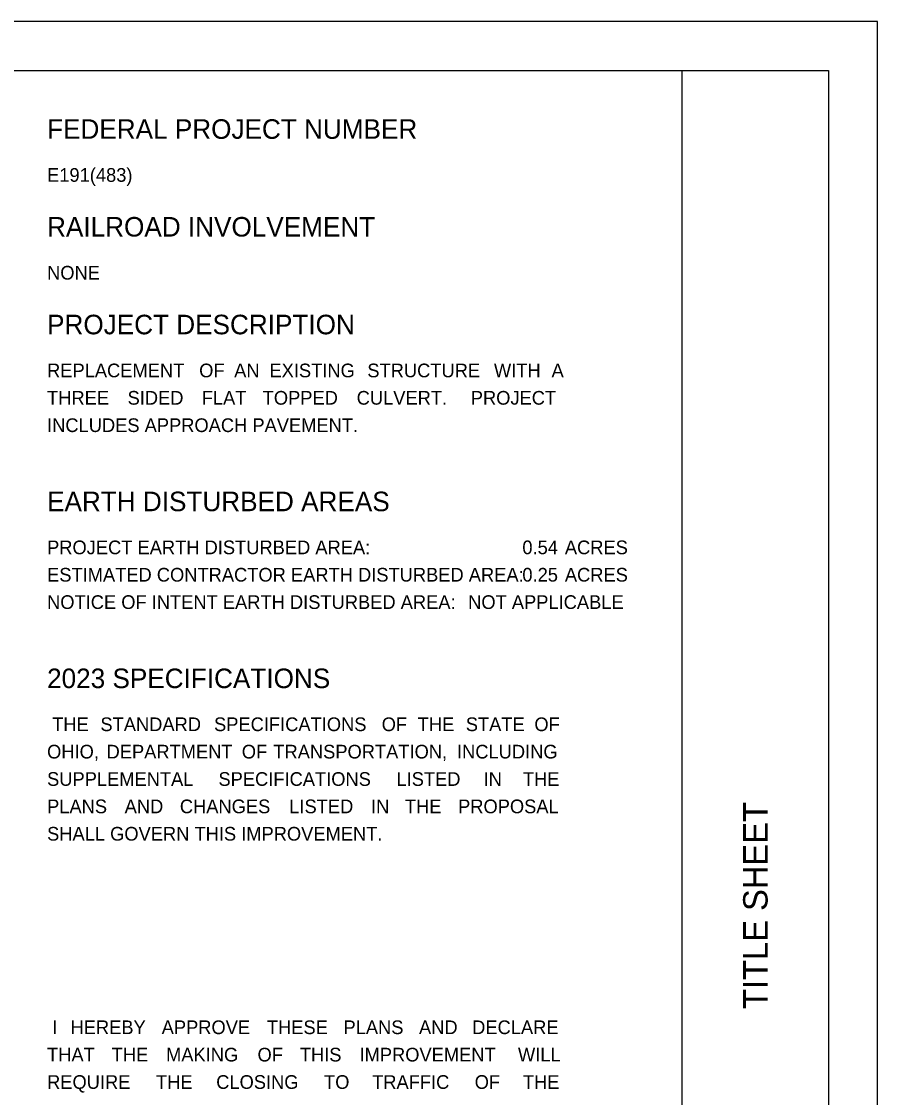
# Model space of a CAD drawing. Extents: x -6.4 to 34, y -1.2 to 22.
# Drawn here: x 25.24 to 34, y 10.99 to 22 of the extents above; entities that cross this region are included whole.
import ezdxf

# ---------------------------------------------------------------- set-up
doc = ezdxf.new("R2010")
doc.units = 0
for name, color, linetype in [('GM_X_County', 7, 'Continuous'), ('GM_X_Section', 7, 'Continuous'), ('GM_X_Township', 7, 'Continuous')]:
    doc.layers.add(name, color=color, linetype=linetype)

msp = doc.modelspace()

# ---------------------------------------------------------------- linework, layer by layer
at = {"layer": 'GM_X_County'}
msp.add_line((32, 0.5), (32, 21.5), dxfattribs=at)
msp.add_lwpolyline([(1.5, 21.5), (33.5, 21.5), (33.5, 0.5), (1.5, 0.5)], close=True, dxfattribs=at)
at = {"layer": 'GM_X_Section'}
msp.add_lwpolyline([(0, 0), (34, 0), (34, 22), (0, 22)], close=True, dxfattribs=at)

# ---------------------------------------------------------------- texts
at = {"layer": 'GM_X_Township'}
for s, height, p in [('FEDERAL PROJECT NUMBER', 0.2, (25.5, 20.8)), ('E191(483)', 0.14, (25.5, 20.36)), ('RAILROAD INVOLVEMENT', 0.2, (25.5, 19.8)), ('NONE', 0.14, (25.5, 19.36)), ('PROJECT DESCRIPTION', 0.2, (25.5, 18.8)), ('REPLACEMENT ', 0.14, (25.5, 18.36)), ('OF ', 0.14, (27.057, 18.36)), ('AN ', 0.14, (27.415, 18.36)), ('EXISTING ', 0.14, (27.776, 18.36)), ('STRUCTURE ', 0.14, (28.778, 18.36)), ('WITH ', 0.14, (30.074, 18.36)), ('A ', 0.14, (30.664, 18.36)), ('THREE ', 0.14, (25.5, 18.08)), ('SIDED ', 0.14, (26.324, 18.08)), ('FLAT ', 0.14, (27.083, 18.08)), ('TOPPED ', 0.14, (27.707, 18.08)), ('CULVERT.  ', 0.14, (28.669, 18.08)), ('PROJECT ', 0.14, (29.837, 18.08)), ('INCLUDES APPROACH PAVEMENT.', 0.14, (25.5, 17.8)), ('EARTH DISTURBED AREAS', 0.2, (25.5, 16.99)), ('PROJECT EARTH DISTURBED AREA:', 0.14, (25.5, 16.55)), ('0.54 ', 0.14, (30.365, 16.55)), ('ACRES', 0.14, (30.8, 16.55)), ('ESTIMATED CONTRACTOR EARTH DISTURBED AREA:', 0.14, (25.5, 16.27)), ('0.25 ', 0.14, (30.365, 16.27)), ('ACRES', 0.14, (30.8, 16.27)), ('NOTICE OF INTENT EARTH DISTURBED AREA:', 0.14, (25.5, 15.99)), ('NOT APPLICABLE', 0.14, (29.81, 15.99)), ('2023 SPECIFICATIONS', 0.2, (25.5, 15.18)), (' THE ', 0.14, (25.5, 14.74)), ('STANDARD ', 0.14, (26.046, 14.74)), ('SPECIFICATIONS ', 0.14, (27.209, 14.74)), ('OF ', 0.14, (28.925, 14.74)), ('THE ', 0.14, (29.294, 14.74)), ('STATE ', 0.14, (29.786, 14.74)), ('OF ', 0.14, (30.488, 14.74)), ('OHIO, ', 0.14, (25.5, 14.46)), ('DEPARTMENT ', 0.14, (26.109, 14.46)), ('OF ', 0.14, (27.493, 14.46)), ('TRANSPORTATION, ', 0.14, (27.816, 14.46)), ('INCLUDING ', 0.14, (29.696, 14.46)), ('SUPPLEMENTAL ', 0.14, (25.5, 14.18)), ('SPECIFICATIONS ', 0.14, (27.254, 14.18)), ('LISTED ', 0.14, (29.076, 14.18)), ('IN ', 0.14, (29.968, 14.18)), ('THE ', 0.14, (30.37, 14.18)), ('PLANS ', 0.14, (25.5, 13.9)), ('AND ', 0.14, (26.294, 13.9)), ('CHANGES ', 0.14, (26.859, 13.9)), ('LISTED ', 0.14, (27.979, 13.9)), ('IN ', 0.14, (28.816, 13.9)), ('THE ', 0.14, (29.163, 13.9)), ('PROPOSAL ', 0.14, (29.707, 13.9)), ('SHALL GOVERN THIS IMPROVEMENT.', 0.14, (25.5, 13.62)), (' I ', 0.14, (25.5, 11.64)), ('HEREBY ', 0.14, (25.74, 11.64)), ('APPROVE ', 0.14, (26.673, 11.64)), ('THESE ', 0.14, (27.75, 11.64)), ('PLANS ', 0.14, (28.534, 11.64)), ('AND ', 0.14, (29.307, 11.64)), ('DECLARE ', 0.14, (29.851, 11.64)), ('THAT ', 0.14, (25.5, 11.36)), ('THE ', 0.14, (26.161, 11.36)), ('MAKING ', 0.14, (26.718, 11.36)), ('OF ', 0.14, (27.654, 11.36)), ('THIS ', 0.14, (28.087, 11.36)), ('IMPROVEMENT ', 0.14, (28.698, 11.36)), ('WILL ', 0.14, (30.32, 11.36)), ('REQUIRE ', 0.14, (25.5, 11.08)), ('THE ', 0.14, (26.615, 11.08)), ('CLOSING ', 0.14, (27.231, 11.08)), ('TO ', 0.14, (28.335, 11.08)), ('TRAFFIC ', 0.14, (28.827, 11.08)), ('OF ', 0.14, (29.877, 11.08)), ('THE ', 0.14, (30.37, 11.08))]:
    msp.add_text(s, height=height, dxfattribs=at).set_placement(p)
msp.add_text('TITLE SHEET', height=0.25, rotation=90, dxfattribs=at).set_placement((32.875, 11.897))

doc.saveas('drawing.dxf')
